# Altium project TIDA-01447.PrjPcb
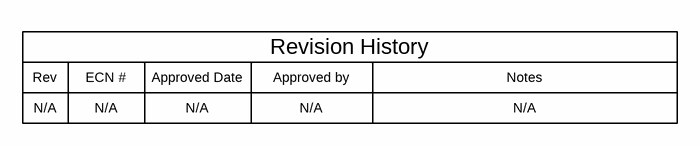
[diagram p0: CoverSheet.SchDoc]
CopyrightYear: 2015; EVM_Orderable: N/A; PCB_Layout: Who did the Layout?; PCB_Rev: E1; PRJ_Customer: Public Release; PRJ_Engineer: Enter name of project lead; PRJ_Number: TIDA-xxxxx; PRJ_Title: Change in menu Project|Project Options|Parameters; SCH_Rev: E1; TechSupport: http://www.ti.com/support; TID: ChangeMe!
3 sheets, 19 parts. Net scope: global (net labels, ports and power ports of the same name join across sheets).
Board file: TIDA-01447 Rev A1.PcbDoc
Sheets:
  CoverSheet.SchDoc
  TIDA-01447.SchDoc
  TID_Hardware.SchDoc

## Sheet CoverSheet.SchDoc
size 431 x 279 mm; Date: Not shown in title block; ApprovedBy: Not shown in title block; CheckedBy: Not shown in title block; Author: Not shown in title block; CompanyName: Not shown in title block; Engineer: Not shown in title block; Organization: Not shown in title block; Address1: Not shown in title block; Address2: Not shown in title block; Address3: Not shown in title block; Address4: Not shown in title block; DocumentNumber: 1; Revision: Use project parameter SCH_Rev; SheetNumber: 1; SheetTotal: 3; PageSetup: Record=PageOptions¦CenterHorizontal=True¦CenterVertical=True¦PrintScale=1.00¦XCorrection=1.00¦YCorrection=1.00¦PrintKind=0¦BorderSize=5000000¦LeftOffset=0¦BottomOffset=0¦Orientation=2¦PaperLength=1000¦PaperWidth=1000¦Scale=100¦PaperSource=15¦PrintQuality=600¦MediaType=1¦DitherType=10¦PaperKind=Letter¦PrintScaleMode=1

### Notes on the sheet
- Rev
- N/A
- ECN #
- Approved Date
- Approved by
- Revision History
- Notes

## Sheet TIDA-01447.SchDoc
size 431 x 279 mm; Date: Not shown in title block; ApprovedBy: Not shown in title block; CheckedBy: Not shown in title block; Author: Not shown in title block; CompanyName: Not shown in title block; Engineer: Not shown in title block; Organization: Not shown in title block; Address1: Not shown in title block; Address2: Not shown in title block; Address3: Not shown in title block; Address4: Not shown in title block; DocumentNumber: 1; Revision: Use project parameter SCH_Rev; SheetNumber: 2; SheetTotal: 3; PageSetup: Record=PageOptions¦CenterHorizontal=True¦CenterVertical=True¦PrintScale=1.00¦XCorrection=1.00¦YCorrection=1.00¦PrintKind=0¦BorderSize=5000000¦LeftOffset=0¦BottomOffset=0¦Orientation=2¦PaperLength=1000¦PaperWidth=1000¦Scale=100¦PaperSource=15¦PrintQuality=600¦MediaType=1¦DitherType=10¦PaperKind=Letter¦PrintScaleMode=1
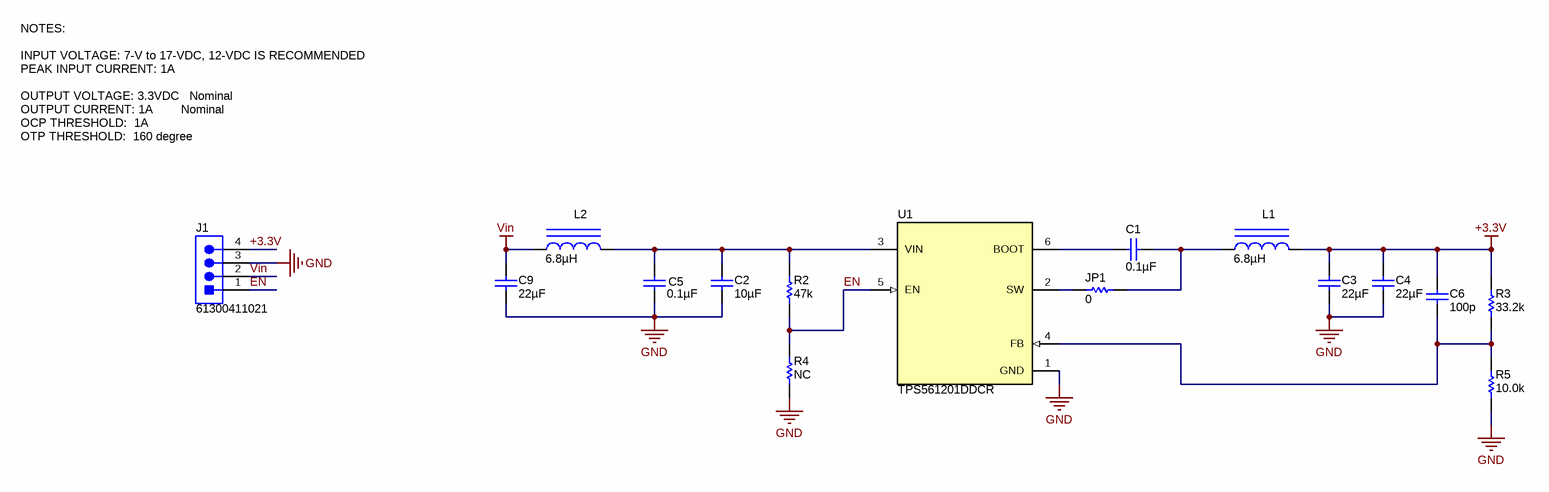
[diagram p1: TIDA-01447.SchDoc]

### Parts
C1  ValueDisplayed: 0.1µF  [0805_HV]  (hidden comment: GRM21BR71E104KA01L)
C2  ValueDisplayed: 10µF  [1206]  (hidden comment: GRM31CR71E106KA12L)
C3  ValueDisplayed: 22µF  [1206_190]  (hidden comment: GCM31CR71A226KE02)
C4  ValueDisplayed: 22µF  [1206_190]  (hidden comment: GCM31CR71A226KE02)
C5  ValueDisplayed: 0.1µF  [0603]  (hidden comment: GRM188R71E104KA01D)
C6  ValueDisplayed: 100p  [C/0805/SMT1]  (hidden comment: 06033C101KAT2A)
C9  ValueDisplayed: 22µF  [1206_190]  (hidden comment: C3216X5R1E226M160AB)
J1  61300411021  [Wurth_61300411021]
JP1  ValueDisplayed: 0  [JUMP-5]  (hidden comment: CRCW0603100KFKEA)
L1  ValueDisplayed: 6.8µH  [LPS8045B]  (hidden comment: ABG06A45M6R8)
L2  ValueDisplayed: 6.8µH  [LPS8045B]  (hidden comment: ABG03A15M6R8)
R2  ValueDisplayed: 47k  [0603]  (hidden comment: CRCW060347K0JNEA)
R3  ValueDisplayed: 33.2k  [0603]  (hidden comment: CRCW060333K2FKEA)
R4  ValueDisplayed: NC  [0603]  (hidden comment: CRCW0603150KFKEA)
R5  ValueDisplayed: 10.0k  [0603]  (hidden comment: CRCW060310K0FKEA)
U1  TPS561201DDCR  [DDC0006A_N]

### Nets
+3.3V: C3.1 C4.1 C6.1 J1.4 L1.2 R3.2
GND: C2.2 C3.2 C4.2 C5.2 C9.2 J1.3 R4.1 R5.1 U1.1(GND)
Vin: C9.1 J1.2 L2.1
EN: J1.1 R2.1 R4.2 U1.5(EN)
NetC1_1: C1.1 JP1.1 L1.1
NetC1_2: C1.2 U1.6(BOOT)
NetC2_1: C2.1 C5.1 L2.2 R2.2 U1.3(VIN)
NetC6_2: C6.2 R3.1 R5.2 U1.4(FB)
NetJP1_2: JP1.2 U1.2(SW)

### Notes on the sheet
- NOTES:
  INPUT VOLTAGE: 7-V to 17-VDC, 12-VDC IS RECOMMENDED
  PEAK INPUT CURRENT: 1A
  OUTPUT VOLTAGE: 3.3VDC   Nominal
  OUTPUT CURRENT: 1A        Nominal
  OCP THRESHOLD:  1A
  OTP THRESHOLD:  160 degree

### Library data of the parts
C1 = GRM21BR71E104KA01L: CAP, CERM, 0.1 µF, 25 V, +/- 10%, X7R, 0805; Manufacturer: MuRata; Polarized: N; CompType: Capacitor; Value: 0.1uF; U/M: EA; Cap_F: 0.0000001; Tolerance_%: 10; Value1: Unknown; VDC_V: 25; Value2: 25V; TaMin_C: -55; TaMax_C: 125; Cap_Case: 0805; AEC Category: Q200
C2 = GRM31CR71E106KA12L: CAP, CERM, 10 µF, 25 V, +/- 10%, X7R, 1206; Manufacturer: MuRata; Polarized: N; CompType: Capacitor; Value: 10uF; U/M: EA; Cap_F: 0.00001; Tolerance_%: 10; Value1: Unknown; VDC_V: 25; Value2: 25V; TaMin_C: -55; TaMax_C: 125; Cap_Case: 2220; AEC Category: Q200
C3 C4 = GCM31CR71A226KE02: CAP, CERM, 22 µF, 10 V, +/- 10%, X7R, AEC-Q200 Grade 1, 1206_190; Manufacturer: MuRata; Polarized: N; CompType: Capacitor; Value: 22uF; U/M: EA; Cap_F: 0.000022; Tolerance_%: 10; Value1: Unknown; Value2: 10V; TaMin_C: -55; TaMax_C: 125; Cap_Case: 1206; AEC Category: Q200; AEC Qualified: Y; AEC Grade: 1
C5 = GRM188R71E104KA01D: CAP, CERM, 0.1 µF, 25 V, +/- 10%, X7R, 0603; Manufacturer: MuRata; Polarized: N; CompType: Capacitor; Value: 0.1uF; U/M: EA; Cap_F: 0.0000001; Tolerance_%: 10; Value1: Unknown; VDC_V: 25; Value2: 25V; TaMin_C: -55; TaMax_C: 125; AEC Category: Q200
C6 = 06033C101KAT2A: CAP, CERM, 100 pF, 25 V, +/- 10%, X7R, 0603; Manufacturer: AVX; Polarized: N; CompType: Capacitor; Value: 100pF; U/M: EA; Cap_F: 0.0000000001; Tolerance_%: 10; Value1: Unknown; VDC_V: 25; Value2: 25V; TaMin_C: -55; TaMax_C: 125; Cap_Case: 0603; AEC Category: Q200
C9 = C3216X5R1E226M160AB: CAP, CERM, 22 µF, 25 V, +/- 20%, X5R, 1206_190; Manufacturer: TDK; Polarized: N; CompType: Capacitor; Value: 22uF; U/M: EA; Cap_F: 0.000022; Tolerance_%: 20; Value1: Unknown; VDC_V: 25; Value2: 25V; TaMin_C: -55; TaMax_C: 85; Cap_Case: 1206; AEC Category: Q200
J1 = 61300411021: Header, 2.54 mm, 4x1, Gold, R/A, TH; Manufacturer: Wurth Elektronik; SymbolCreator: a0412235; Pitch_mm: 2.54; Gender: Male; Shrouded: N; Row_Count: 1
JP1 = CRCW0603100KFKEA: RES, 100 k, 1%, 0.1 W, 0603; Manufacturer: Vishay-Dale; CompType: Resistor; Value: 100k; Res_ohm: 100000; Tolerance_%: 1; Power_W: 0.1; Value2: 0.1W; VDC_V: 75; TempCo: 100 ppm/C; EIA_Code: E96; U/M: EA; AEC Category: Q200
L1 = LPS8045B-333MRB: Inductor, Shielded, Ferrite, 3.3 µH, 6.08 A, SMD; Manufacturer: Coilcraft; Value: 6.8uH; Ind_H: 33.0E-6; Imax_A: 1.2; Irms: 1.2A @ 20C rise; Isat: 1.8A @ 10% inductance drop; DCR_ohm: 0.121; Value1: 0.121 ohm; Value2: 6.08A; AEC Category: Q200; AEC Qualified: N
L2 = LPS8045B-333MRB: Inductor, Shielded, Ferrite, 6.8 µH, 3.3 A, SMD; Manufacturer: Coilcraft; Value: 6.8uH; Ind_H: 33.0E-6; Imax_A: 1.2; Irms: 1.2A @ 20C rise; Isat: 1.8A @ 10% inductance drop; DCR_ohm: 0.121; Value1: 0.121 ohm; Value2: 0.88A; AEC Category: Q200; AEC Qualified: N
R2 = CRCW060347K0JNEA: RES, 47 k, 5%, 0.1 W, 0603; Manufacturer: Vishay-Dale; CompType: Resistor; Value: 47k; Res_ohm: 47000; Value_Code: 47k0; Tolerance_%: 5; Power_W: 0.1; Value2: 0.1W; VDC_V: 75; TempCo: 200 ppm/C; EIA_Code: E24; U/M: EA; AEC Category: Q200
R3 = CRCW060333K2FKEA: RES, 33.2 k, 1%, 0.1 W, 0603; Manufacturer: Vishay-Dale; CompType: Resistor; Value: 33.2k; Res_ohm: 33200; Value_Code: 33k2; Tolerance_%: 1; Power_W: 0.1; Value2: 0.1W; VDC_V: 75; TempCo: 100 ppm/C; EIA_Code: E96; U/M: EA; AEC Category: Q200
R4 = CRCW0603150KFKEA: RES, 150 k, 1%, 0.1 W, 0603; Manufacturer: Vishay-Dale; CompType: Resistor; Value: 150k; Res_ohm: 150000; Tolerance_%: 1; Power_W: 0.1; Value2: 0.1W; VDC_V: 75; TempCo: 100 ppm/C; EIA_Code: E96; U/M: EA; AEC Category: Q200
R5 = CRCW060310K0FKEA: RES, 10.0 k, 1%, 0.1 W, 0603; Manufacturer: Vishay-Dale; CompType: Resistor; Value: 10.0k; Res_ohm: 10000; Value_Code: 10k0; Tolerance_%: 1; Power_W: 0.1; Value2: 0.1W; VDC_V: 75; TempCo: 100 ppm/C; EIA_Code: E96; U/M: EA; AEC Category: Q200
U1 = TPS54202DDCR: 4.5-V TO 28-V INPUT, 2-A OUTPUT, EMI FRIENDLY SYNCHRONUOUS STEP-DOWN CONVERTOR, DDC0006A; Alternate PartNumber: TPS54202DDCT; Manufacturer: Texas Instruments; SymbolCreator: a0411947; CompType: IC; U/M: EA

## Sheet TID_Hardware.SchDoc
size 431 x 279 mm; Date: Not shown in title block; ApprovedBy: Not shown in title block; CheckedBy: Not shown in title block; Author: Not shown in title block; CompanyName: Not shown in title block; Engineer: Not shown in title block; Organization: Not shown in title block; Address1: Not shown in title block; Address2: Not shown in title block; Address3: Not shown in title block; Address4: Not shown in title block; DocumentNumber: 1; Revision: Use project parameter SCH_Rev; SheetNumber: 3; SheetTotal: 3; PageSetup: Record=PageOptions¦CenterHorizontal=True¦CenterVertical=True¦PrintScale=1.00¦XCorrection=1.00¦YCorrection=1.00¦PrintKind=0¦BorderSize=5000000¦LeftOffset=0¦BottomOffset=0¦Orientation=2¦PaperLength=1000¦PaperWidth=1000¦Scale=100¦PaperSource=15¦PrintQuality=600¦MediaType=1¦DitherType=10¦PaperKind=Letter¦PrintScaleMode=1
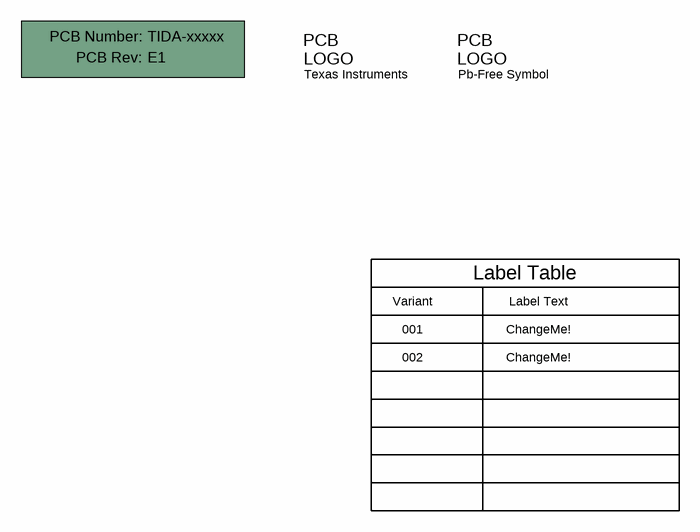
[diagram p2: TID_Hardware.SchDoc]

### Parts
!PCB  Printed Circuit Board  (value not drawn)  (mechanical)
Logo1  Texas Instruments  [TI_Stacked_Overlay_Small]  (no BOM)
Logo2  Pb-Free Symbol  [Pb-Free_Overlay_Small]  (no BOM)

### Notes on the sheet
- Variant
- Label Table
- Label Text
- 001
- 002
- ChangeMe!

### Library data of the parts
!PCB = PCB: Manufacturer: Any; PartNumber: TIDA-xxxxx; SymbolCreator: a0412235
Logo1 = TI_Logo: Texas Instrument Corporate Signature; SymbolCreator: codlsc
Logo2 = Pb-Free: SymbolCreator: a0412235

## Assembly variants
001: not fitted FID1 FID2 FID3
